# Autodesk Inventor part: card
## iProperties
Author: Elise Moss
Created: 2001-09
Part Number: card
Document SubType Name: Modeling
Designer: Elise Moss
Control State: 0
Master: False
Checked Out: False
PropertySet Name: Design Tracking Control
Shininess: 64.0
Angle Display Precision: 2
Document Length Units: 11272
Document Angle Units: 11286
Document Time Units: 11279
Document Mass Units: 11290
Document Length Units Precision: 3
Document Angle Units Precision: 2
Compacted: True
PropertySet Name: _Private Model Information
Density: 0.0
Volumn: 0.0
Area: 0.0
PropertySet Name: Model Information
